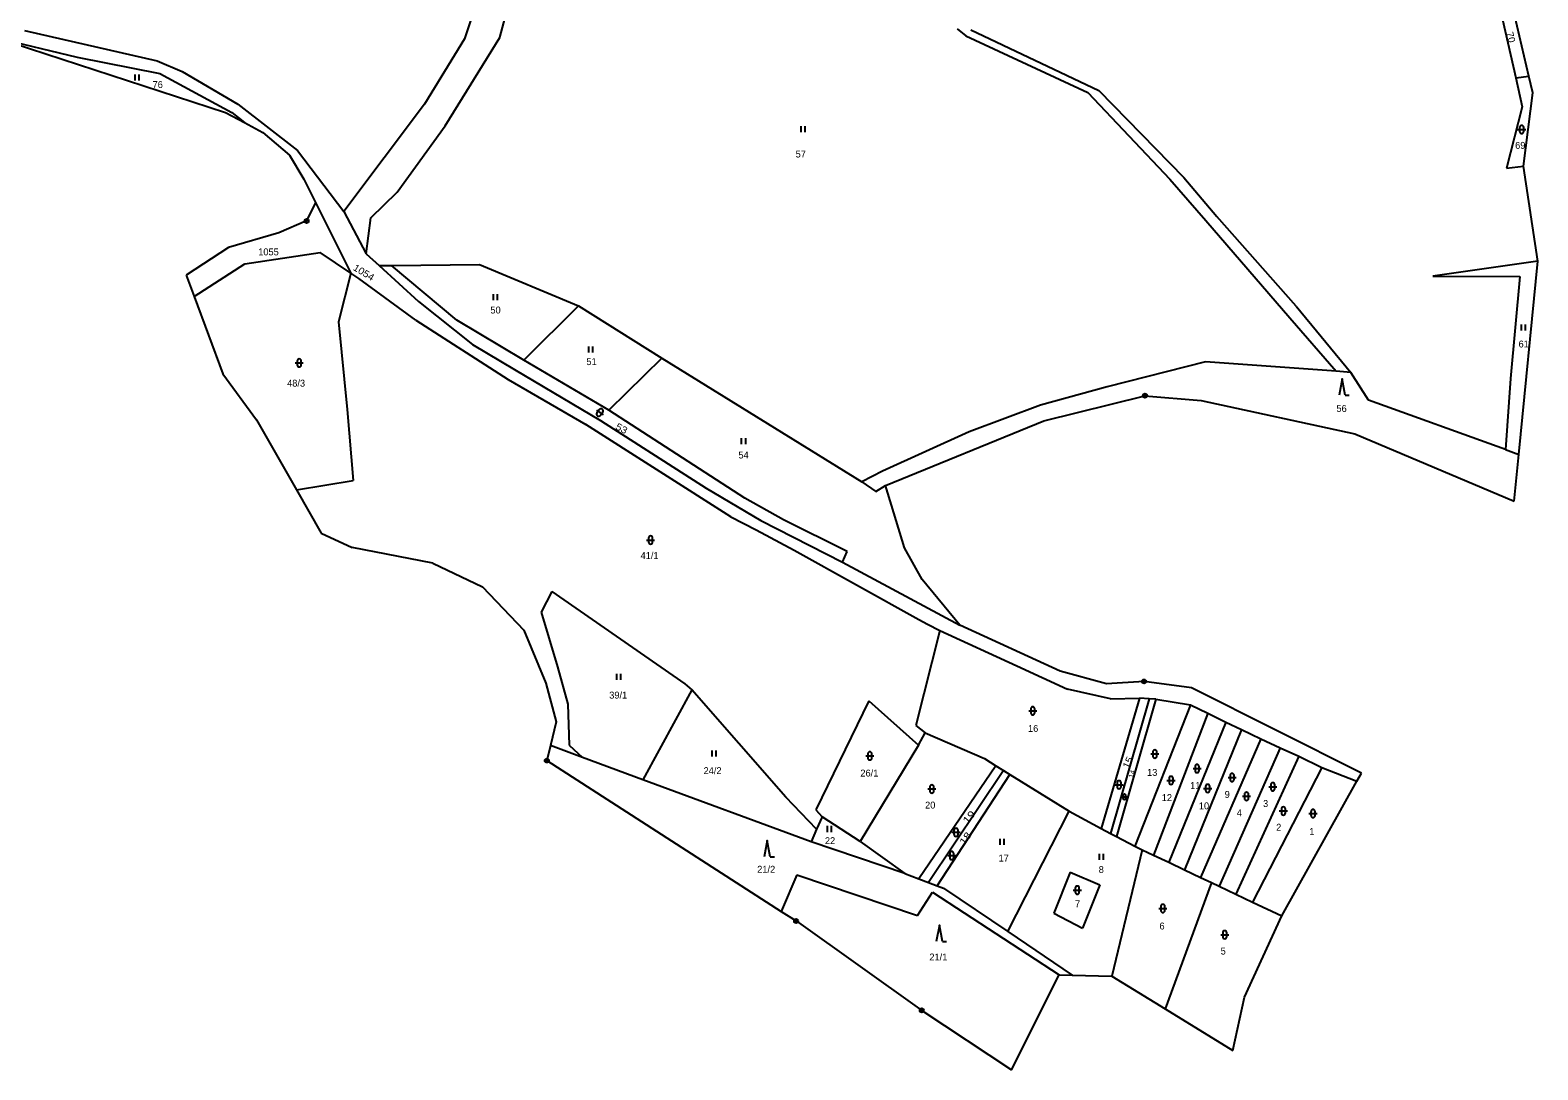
# Model space of a CAD drawing. Extents: x -744132 to -742433, y -984679 to -982287.
# Drawn here: x -742804.5 to -742433.4, y -984679 to -984423.2 of the extents above; entities that cross this region are included whole.
import ezdxf

# ---------------------------------------------------------------- set-up
doc = ezdxf.new("R2010")
doc.units = 0
doc.header["$LTSCALE"] = 0.68
for name, color, linetype, lineweight in [('1', 7, 'Continuous', 25), ('3', 7, 'Continuous', 25), ('8', 7, 'Continuous', 25)]:
    doc.layers.add(name, color=color, linetype=linetype, lineweight=lineweight)
doc.layers.add('2', color=7, linetype='Continuous')

msp = doc.modelspace()

# ---------------------------------------------------------------- linework, layer by layer
at = {"layer": '1'}
for p, q in [((-742686.64, -984392.91), (-742697.63, -984425.32)), ((-742688.87, -984424.99), (-742683.18, -984403.1)), ((-742443.84, -984412.74), (-742438.78, -984434.87)), ((-742435.57, -984434.53), (-742440.79, -984412.23)), ((-742805.92, -984423.24), (-742773.27, -984430.71)), ((-742576.33, -984422.81), (-742574.19, -984424.53)), ((-742572.92, -984423.1), (-742541.44, -984438.02)), ((-742812.82, -984425.09), (-742756.42, -984443.42)), ((-742812.82, -984425.09), (-742792.97, -984429.85)), ((-742697.63, -984425.32), (-742707.47, -984441.42)), ((-742702.33, -984446.74), (-742688.87, -984424.99)), ((-742574.19, -984424.53), (-742544.19, -984438.51)), ((-742792.97, -984429.85), (-742772.63, -984433.86)), ((-742773.27, -984430.71), (-742767.1, -984433.32)), ((-742772.63, -984433.86), (-742754.86, -984443.45)), ((-742767.1, -984433.32), (-742753.38, -984441.39)), ((-742438.78, -984434.87), (-742435.57, -984434.53)), ((-742438.78, -984434.87), (-742437.22, -984442.01)), ((-742434.62, -984438.58), (-742435.57, -984434.53)), ((-742544.19, -984438.51), (-742523.93, -984459.88)), ((-742541.44, -984438.02), (-742520.52, -984459.47)), ((-742436.89, -984456.67), (-742434.62, -984438.58)), ((-742753.38, -984441.39), (-742738.7, -984452.76)), ((-742707.47, -984441.42), (-742727.28, -984467.78)), ((-742437.22, -984442.01), (-742441.06, -984457.16)), ((-742756.42, -984443.42), (-742751.74, -984445.92)), ((-742754.86, -984443.45), (-742751.74, -984445.92)), ((-742751.74, -984445.92), (-742747.24, -984448.32)), ((-742747.24, -984448.32), (-742740.7, -984453.97)), ((-742714.21, -984463.04), (-742702.33, -984446.74)), ((-742740.7, -984453.97), (-742737.18, -984459.85)), ((-742441.06, -984457.16), (-742436.89, -984456.67)), ((-742433.38, -984480), (-742436.89, -984456.67)), ((-742737.18, -984459.85), (-742734.28, -984465.58)), ((-742523.93, -984459.88), (-742515.07, -984470.05)), ((-742520.52, -984459.47), (-742512.4, -984469)), ((-742720.62, -984469.38), (-742714.21, -984463.04)), ((-742734.28, -984465.58), (-742736.47, -984470.13)), ((-742734.28, -984465.58), (-742725.54, -984483)), ((-742736.47, -984470.13), (-742743.28, -984473.08)), ((-742721.84, -984478.21), (-742720.62, -984469.38)), ((-742515.07, -984470.05), (-742494.47, -984493.95)), ((-742492.9, -984491.09), (-742512.4, -984469)), ((-742743.28, -984473.08), (-742755.72, -984476.65)), ((-742755.72, -984476.65), (-742766.07, -984483.46)), ((-742751.7, -984480.69), (-742733.14, -984477.92)), ((-742725.54, -984483), (-742733.14, -984477.92)), ((-742721.84, -984478.21), (-742718.62, -984481.12)), ((-742433.38, -984480), (-742459.23, -984483.72)), ((-742438.1, -984527.59), (-742433.38, -984480)), ((-742766.07, -984483.46), (-742764.15, -984488.68)), ((-742764.15, -984488.68), (-742751.7, -984480.69)), ((-742725.54, -984483), (-742728.62, -984494.92)), ((-742723.64, -984484.28), (-742725.54, -984483)), ((-742718.62, -984481.12), (-742715.55, -984481.06)), ((-742718.62, -984481.12), (-742708.88, -984489.94)), ((-742715.55, -984481.06), (-742693.94, -984480.84)), ((-742699.46, -984494.54), (-742715.55, -984481.06)), ((-742693.94, -984480.84), (-742669.5, -984491)), ((-742459.23, -984483.72), (-742437.82, -984483.8)), ((-742437.82, -984483.8), (-742440.08, -984508.93)), ((-742709.61, -984494.5), (-742723.64, -984484.28)), ((-742764.15, -984488.68), (-742757.11, -984507.78)), ((-742708.88, -984489.94), (-742695.61, -984500.55)), ((-742669.5, -984491), (-742682.95, -984504.39)), ((-742669.5, -984491), (-742649.04, -984503.92)), ((-742492.9, -984491.09), (-742479.4, -984507.38)), ((-742728.62, -984494.92), (-742726.49, -984516.5)), ((-742709.61, -984494.5), (-742686.88, -984509.16)), ((-742682.95, -984504.39), (-742699.46, -984494.54)), ((-742494.47, -984493.95), (-742483.02, -984507.12)), ((-742695.61, -984500.55), (-742685.32, -984506.7)), ((-742662.08, -984516.66), (-742682.95, -984504.39)), ((-742649.04, -984503.92), (-742662.08, -984516.66)), ((-742649.04, -984503.92), (-742599.77, -984534.36)), ((-742515.19, -984504.78), (-742539.43, -984510.92)), ((-742483.02, -984507.12), (-742515.19, -984504.78)), ((-742757.11, -984507.78), (-742748.76, -984519.05)), ((-742686.88, -984509.16), (-742667.69, -984520.25)), ((-742685.32, -984506.7), (-742664.11, -984519.23)), ((-742479.4, -984507.38), (-742483.02, -984507.12)), ((-742475.08, -984514.22), (-742479.4, -984507.38)), ((-742440.08, -984508.93), (-742441.34, -984526.33)), ((-742539.43, -984510.92), (-742555.77, -984515.48)), ((-742554.97, -984519.32), (-742530.1, -984513.12)), ((-742530.1, -984513.12), (-742516.26, -984514.3)), ((-742726.49, -984516.5), (-742725, -984533.99)), ((-742628.57, -984538.37), (-742662.08, -984516.66)), ((-742555.77, -984515.48), (-742573.38, -984522.02)), ((-742516.26, -984514.3), (-742478.43, -984522.49)), ((-742441.34, -984526.33), (-742475.08, -984514.22)), ((-742748.76, -984519.05), (-742738.91, -984536.33)), ((-742632, -984542.91), (-742667.69, -984520.25)), ((-742664.11, -984519.23), (-742638.1, -984535.86)), ((-742593.93, -984535.26), (-742554.97, -984519.32)), ((-742573.38, -984522.02), (-742594.73, -984531.71)), ((-742478.43, -984522.49), (-742439.24, -984539.06)), ((-742441.34, -984526.33), (-742438.1, -984527.59)), ((-742439.24, -984539.06), (-742438.1, -984527.59)), ((-742594.73, -984531.71), (-742599.77, -984534.36)), ((-742738.91, -984536.33), (-742725, -984533.99)), ((-742599.77, -984534.36), (-742596.31, -984536.74)), ((-742596.31, -984536.74), (-742593.93, -984535.26)), ((-742589.29, -984550.55), (-742593.93, -984535.26)), ((-742738.91, -984536.33), (-742732.87, -984546.93)), ((-742638.1, -984535.86), (-742624.66, -984543.84)), ((-742619.11, -984543.68), (-742628.57, -984538.37)), ((-742632, -984542.91), (-742625.81, -984546.14)), ((-742625.81, -984546.14), (-742616.44, -984551.15)), ((-742624.66, -984543.84), (-742604.56, -984554.07)), ((-742603.41, -984551.46), (-742619.11, -984543.68)), ((-742732.87, -984546.93), (-742725.28, -984550.46)), ((-742705.39, -984554.38), (-742725.28, -984550.46)), ((-742584.9, -984558.39), (-742589.29, -984550.55)), ((-742616.44, -984551.15), (-742585.78, -984568.2)), ((-742604.56, -984554.07), (-742603.41, -984551.46)), ((-742604.56, -984554.07), (-742575.65, -984569.59)), ((-742705.39, -984554.38), (-742693.14, -984560.18)), ((-742693.14, -984560.18), (-742683.01, -984570.81)), ((-742676.11, -984561.3), (-742678.71, -984566.36)), ((-742676.11, -984561.3), (-742643.34, -984584)), ((-742575.65, -984569.59), (-742584.9, -984558.39)), ((-742678.71, -984566.36), (-742674.71, -984579.83)), ((-742585.78, -984568.2), (-742583.65, -984569.34)), ((-742683.01, -984570.81), (-742677.6, -984583.87)), ((-742580.59, -984570.91), (-742561.67, -984579.62)), ((-742550.93, -984580.91), (-742575.65, -984569.59)), ((-742674.71, -984579.83), (-742672.17, -984589)), ((-742561.67, -984579.62), (-742549.17, -984585.35)), ((-742677.6, -984583.87), (-742675.07, -984593.37)), ((-742643.34, -984584), (-742641.62, -984585.48)), ((-742539.6, -984584.04), (-742550.93, -984580.91)), ((-742530.31, -984583.45), (-742539.6, -984584.04)), ((-742518.63, -984584.98), (-742530.31, -984583.45)), ((-742641.62, -984585.48), (-742653.69, -984607.63)), ((-742618.47, -984611.95), (-742641.62, -984585.48)), ((-742538.6, -984587.71), (-742549.17, -984585.35)), ((-742531.44, -984587.6), (-742540.9, -984619.6)), ((-742538.6, -984587.71), (-742531.44, -984587.6)), ((-742529.05, -984587.71), (-742538.55, -984620.83)), ((-742529.05, -984587.71), (-742531.44, -984587.6)), ((-742527.43, -984587.79), (-742529.05, -984587.71)), ((-742476.82, -984606.04), (-742518.63, -984584.98)), ((-742672.17, -984589), (-742671.81, -984599.12)), ((-742598.03, -984588.23), (-742611.11, -984615.06)), ((-742598.03, -984588.23), (-742585.85, -984599.09)), ((-742527.43, -984587.79), (-742537.11, -984621.58)), ((-742518.91, -984589.19), (-742532.55, -984624.01)), ((-742514.6, -984591.28), (-742528.03, -984626.16)), ((-742527.43, -984587.79), (-742518.91, -984589.19)), ((-742518.91, -984589.19), (-742514.6, -984591.28)), ((-742514.6, -984591.28), (-742510.17, -984593.43)), ((-742675.07, -984593.37), (-742676.46, -984599.25)), ((-742586.52, -984594.31), (-742584.19, -984596.12)), ((-742510.17, -984593.43), (-742524.24, -984627.96)), ((-742510.17, -984593.43), (-742506.32, -984595.3)), ((-742585.85, -984599.09), (-742584.19, -984596.12)), ((-742584.19, -984596.12), (-742569.62, -984602.45)), ((-742506.32, -984595.3), (-742520.34, -984629.81)), ((-742501.58, -984597.6), (-742516.43, -984631.66)), ((-742506.32, -984595.3), (-742501.58, -984597.6)), ((-742501.58, -984597.6), (-742496.8, -984599.79)), ((-742676.46, -984599.25), (-742677.33, -984602.93)), ((-742668.52, -984602.17), (-742676.46, -984599.25)), ((-742671.81, -984599.12), (-742668.52, -984602.17)), ((-742653.69, -984607.63), (-742668.52, -984602.17)), ((-742585.85, -984599.09), (-742600.21, -984622.87)), ((-742569.62, -984602.45), (-742566.78, -984604.21)), ((-742496.8, -984599.79), (-742511.82, -984633.84)), ((-742492.21, -984601.87), (-742507.73, -984635.78)), ((-742496.8, -984599.79), (-742492.21, -984601.87)), ((-742492.21, -984601.87), (-742486.59, -984604.65)), ((-742677.33, -984602.93), (-742619.64, -984640.05)), ((-742566.78, -984604.21), (-742585.76, -984632.01)), ((-742564.94, -984605.35), (-742583.38, -984632.94)), ((-742566.78, -984604.21), (-742564.94, -984605.35)), ((-742564.94, -984605.35), (-742563.36, -984606.33)), ((-742486.59, -984604.65), (-742503.61, -984637.74)), ((-742486.59, -984604.65), (-742477.9, -984607.97)), ((-742477.9, -984607.97), (-742476.82, -984606.04)), ((-742612.28, -984622.88), (-742653.69, -984607.63)), ((-742581.28, -984633.76), (-742563.36, -984606.33)), ((-742563.36, -984606.33), (-742548.73, -984615.39)), ((-742496.41, -984641.15), (-742477.9, -984607.97)), ((-742610.97, -984619.82), (-742618.47, -984611.95)), ((-742611.11, -984615.06), (-742609.55, -984616.79)), ((-742609.55, -984616.79), (-742610.97, -984619.82)), ((-742600.21, -984622.87), (-742609.55, -984616.79)), ((-742563.81, -984645.01), (-742548.73, -984615.39)), ((-742548.73, -984615.39), (-742540.9, -984619.6)), ((-742610.97, -984619.82), (-742612.28, -984622.88)), ((-742540.9, -984619.6), (-742538.55, -984620.83)), ((-742538.55, -984620.83), (-742537.11, -984621.58)), ((-742589.18, -984630.69), (-742612.28, -984622.88)), ((-742600.21, -984622.87), (-742589.18, -984630.69)), ((-742537.11, -984621.58), (-742532.55, -984624.01)), ((-742532.55, -984624.01), (-742530.75, -984624.87)), ((-742530.75, -984624.87), (-742538.23, -984655.97)), ((-742530.75, -984624.87), (-742528.03, -984626.16)), ((-742528.03, -984626.16), (-742524.24, -984627.96)), ((-742524.24, -984627.96), (-742520.34, -984629.81)), ((-742615.82, -984631.07), (-742619.64, -984640.05)), ((-742615.82, -984631.07), (-742586.11, -984641.07)), ((-742589.18, -984630.69), (-742585.76, -984632.01)), ((-742585.76, -984632.01), (-742583.38, -984632.94)), ((-742548.52, -984630.36), (-742552.49, -984640.45)), ((-742548.52, -984630.36), (-742541.17, -984633.54)), ((-742520.34, -984629.81), (-742516.43, -984631.66)), ((-742516.43, -984631.66), (-742513.71, -984632.95)), ((-742586.11, -984641.07), (-742582.36, -984635.29)), ((-742583.38, -984632.94), (-742581.28, -984633.76)), ((-742582.36, -984635.29), (-742551.21, -984655.68)), ((-742581.28, -984633.76), (-742579.67, -984634.36)), ((-742579.67, -984634.36), (-742563.81, -984645.01)), ((-742541.17, -984633.54), (-742545.44, -984644.15)), ((-742513.71, -984632.95), (-742525.09, -984664.05)), ((-742513.71, -984632.95), (-742511.82, -984633.84)), ((-742511.82, -984633.84), (-742507.73, -984635.78)), ((-742507.73, -984635.78), (-742503.61, -984637.74)), ((-742503.61, -984637.74), (-742496.41, -984641.15)), ((-742619.64, -984640.05), (-742615.98, -984642.4)), ((-742615.98, -984642.4), (-742585.04, -984664.39)), ((-742552.49, -984640.45), (-742545.44, -984644.15)), ((-742505.61, -984661.14), (-742496.41, -984641.15)), ((-742563.81, -984645.01), (-742547.99, -984655.75)), ((-742562.98, -984679.03), (-742551.21, -984655.68)), ((-742551.21, -984655.68), (-742547.99, -984655.75)), ((-742547.99, -984655.75), (-742538.23, -984655.97)), ((-742538.23, -984655.97), (-742525.09, -984664.05)), ((-742508.48, -984674.26), (-742505.61, -984661.14)), ((-742585.04, -984664.39), (-742562.98, -984679.03)), ((-742525.09, -984664.05), (-742508.48, -984674.26))]:
    msp.add_line(p, q, dxfattribs=at)
for points in [[(-742738.7, -984452.76), (-742727.28, -984467.78), (-742721.84, -984478.21)], [(-742583.65, -984569.34), (-742580.59, -984570.91), (-742586.52, -984594.31)]]:
    msp.add_lwpolyline(points, dxfattribs=at)
at = {"layer": '3'}
for p, q in [((-742778.701, -984435.57), (-742778.701, -984434.07)), ((-742777.7, -984435.57), (-742777.7, -984434.07)), ((-742614.741, -984448.27), (-742614.741, -984446.77)), ((-742613.74, -984448.27), (-742613.74, -984446.77)), ((-742438.361, -984447.611), (-742436.359, -984447.611)), ((-742437.861, -984447.111), (-742437.861, -984448.112)), ((-742436.859, -984448.112), (-742436.859, -984447.111)), ((-742690.481, -984489.6), (-742690.481, -984488.1)), ((-742689.48, -984489.6), (-742689.48, -984488.1)), ((-742437.391, -984497.08), (-742437.391, -984495.58)), ((-742436.39, -984497.08), (-742436.39, -984495.58)), ((-742667.001, -984502.51), (-742667.001, -984501.01)), ((-742666, -984502.51), (-742666, -984501.01)), ((-742739.281, -984505.061), (-742737.279, -984505.061)), ((-742738.781, -984504.561), (-742738.781, -984505.562)), ((-742737.779, -984505.562), (-742737.779, -984504.561)), ((-742480.8, -984513), (-742479.804, -984513)), ((-742665.093, -984516.673), (-742663.473, -984517.85)), ((-742664.394, -984516.563), (-742664.982, -984517.373)), ((-742664.172, -984517.961), (-742663.584, -984517.151)), ((-742629.381, -984525.07), (-742629.381, -984523.57)), ((-742628.38, -984525.07), (-742628.38, -984523.57)), ((-742652.791, -984548.641), (-742650.789, -984548.641)), ((-742652.291, -984548.141), (-742652.291, -984549.142)), ((-742651.289, -984549.142), (-742651.289, -984548.141)), ((-742660.131, -984583.09), (-742660.131, -984581.59)), ((-742659.13, -984583.09), (-742659.13, -984581.59)), ((-742558.711, -984590.681), (-742556.709, -984590.681)), ((-742558.211, -984590.181), (-742558.211, -984591.182)), ((-742557.209, -984591.182), (-742557.209, -984590.181)), ((-742636.671, -984601.91), (-742636.671, -984600.41)), ((-742635.67, -984601.91), (-742635.67, -984600.41)), ((-742598.811, -984601.771), (-742596.809, -984601.771)), ((-742598.311, -984601.271), (-742598.311, -984602.272)), ((-742597.309, -984602.272), (-742597.309, -984601.271)), ((-742528.661, -984601.291), (-742526.659, -984601.291)), ((-742528.161, -984600.791), (-742528.161, -984601.792)), ((-742527.159, -984601.792), (-742527.159, -984600.791)), ((-742518.261, -984604.881), (-742516.259, -984604.881)), ((-742517.761, -984604.381), (-742517.761, -984605.382)), ((-742516.759, -984605.382), (-742516.759, -984604.381)), ((-742583.551, -984609.911), (-742581.549, -984609.911)), ((-742583.051, -984609.411), (-742583.051, -984610.412)), ((-742582.049, -984610.412), (-742582.049, -984609.411)), ((-742537.461, -984608.871), (-742535.459, -984608.871)), ((-742536.961, -984608.371), (-742536.961, -984609.372)), ((-742535.959, -984609.372), (-742535.959, -984608.371)), ((-742524.671, -984607.801), (-742522.669, -984607.801)), ((-742524.171, -984607.301), (-742524.171, -984608.302)), ((-742523.169, -984608.302), (-742523.169, -984607.301)), ((-742515.651, -984609.771), (-742513.649, -984609.771)), ((-742515.151, -984609.271), (-742515.151, -984610.272)), ((-742514.149, -984610.272), (-742514.149, -984609.271)), ((-742509.651, -984607.081), (-742507.649, -984607.081)), ((-742509.151, -984606.581), (-742509.151, -984607.582)), ((-742508.149, -984607.582), (-742508.149, -984606.581)), ((-742499.631, -984609.371), (-742497.629, -984609.371)), ((-742499.131, -984608.871), (-742499.131, -984609.872)), ((-742498.129, -984609.872), (-742498.129, -984608.871)), ((-742535.861, -984611.831), (-742534.459, -984611.831)), ((-742535.51, -984611.48), (-742535.51, -984612.181)), ((-742534.81, -984612.181), (-742534.81, -984611.48)), ((-742506.101, -984611.721), (-742504.099, -984611.721)), ((-742505.601, -984611.221), (-742505.601, -984612.222)), ((-742504.599, -984612.222), (-742504.599, -984611.221)), ((-742497.021, -984615.321), (-742495.019, -984615.321)), ((-742496.521, -984614.821), (-742496.521, -984615.822)), ((-742495.519, -984615.822), (-742495.519, -984614.821)), ((-742489.721, -984615.951), (-742487.719, -984615.951)), ((-742489.221, -984615.451), (-742489.221, -984616.452)), ((-742488.219, -984616.452), (-742488.219, -984615.451)), ((-742608.241, -984620.5), (-742608.241, -984619)), ((-742607.24, -984620.5), (-742607.24, -984619)), ((-742577.601, -984620.581), (-742575.599, -984620.581)), ((-742577.101, -984620.081), (-742577.101, -984621.082)), ((-742576.099, -984621.082), (-742576.099, -984620.081)), ((-742565.771, -984623.65), (-742565.771, -984622.15)), ((-742564.77, -984623.65), (-742564.77, -984622.15)), ((-742622.32, -984626.57), (-742621.324, -984626.57)), ((-742578.651, -984626.291), (-742576.649, -984626.291)), ((-742578.151, -984625.791), (-742578.151, -984626.792)), ((-742577.149, -984626.792), (-742577.149, -984625.791)), ((-742541.291, -984627.35), (-742541.291, -984625.85)), ((-742540.29, -984627.35), (-742540.29, -984625.85)), ((-742547.751, -984634.801), (-742545.749, -984634.801)), ((-742547.251, -984634.301), (-742547.251, -984635.302)), ((-742546.249, -984635.302), (-742546.249, -984634.301)), ((-742526.701, -984639.311), (-742524.699, -984639.311)), ((-742526.201, -984638.811), (-742526.201, -984639.812)), ((-742525.199, -984639.812), (-742525.199, -984638.811)), ((-742511.451, -984645.781), (-742509.449, -984645.781)), ((-742510.951, -984645.281), (-742510.951, -984646.282)), ((-742509.949, -984646.282), (-742509.949, -984645.281)), ((-742579.96, -984647.45), (-742578.964, -984647.45))]:
    msp.add_line(p, q, dxfattribs=at)
for points in [[(-742480.8, -984513), (-742481.55, -984509), (-742482.3, -984513)], [(-742622.32, -984626.57), (-742623.07, -984622.57), (-742623.82, -984626.57)], [(-742579.96, -984647.45), (-742580.71, -984643.45), (-742581.46, -984647.45)]]:
    msp.add_lwpolyline(points, dxfattribs=at)
for centre, radius, start, end in [((-742437.36, -984447.1109), 0.5, 0, 180), ((-742437.36, -984448.1109), 0.5, 180, 359.98789), ((-742738.28, -984504.5609), 0.5, 0, 180), ((-742738.28, -984505.5609), 0.5, 180, 359.98789), ((-742663.9889, -984516.8572), 0.5, 324, 144), ((-742664.5766, -984517.6662), 0.5, 144, 323.98789), ((-742651.79, -984548.1409), 0.5, 0, 180), ((-742651.79, -984549.1409), 0.5, 180, 359.98789), ((-742557.71, -984590.1809), 0.5, 0, 180), ((-742557.71, -984591.1809), 0.5, 180, 359.98789), ((-742597.81, -984601.2709), 0.5, 0, 180), ((-742597.81, -984602.2709), 0.5, 180, 359.98789), ((-742527.66, -984600.7909), 0.5, 0, 180), ((-742527.66, -984601.7909), 0.5, 180, 359.98789), ((-742517.26, -984604.3809), 0.5, 0, 180), ((-742517.26, -984605.3809), 0.5, 180, 359.98789), ((-742508.65, -984606.5809), 0.5, 0, 180), ((-742582.55, -984609.4109), 0.5, 0, 180), ((-742536.46, -984608.3709), 0.5, 0, 180), ((-742536.46, -984609.3709), 0.5, 180, 359.98789), ((-742523.67, -984607.3009), 0.5, 0, 180), ((-742523.67, -984608.3009), 0.5, 180, 359.98789), ((-742514.65, -984609.2709), 0.5, 0, 180), ((-742508.65, -984607.5809), 0.5, 180, 359.98789), ((-742498.63, -984608.8709), 0.5, 0, 180), ((-742498.63, -984609.8709), 0.5, 180, 359.98789), ((-742582.55, -984610.4109), 0.5, 180, 359.98789), ((-742535.16, -984611.4806), 0.35, 0, 180), ((-742535.16, -984612.1806), 0.35, 180, 359.98789), ((-742514.65, -984610.2709), 0.5, 180, 359.98789), ((-742505.1, -984611.2209), 0.5, 0, 180), ((-742505.1, -984612.2209), 0.5, 180, 359.98789), ((-742496.02, -984614.8209), 0.5, 0, 180), ((-742496.02, -984615.8209), 0.5, 180, 359.98789), ((-742488.72, -984615.4509), 0.5, 0, 180), ((-742488.72, -984616.4509), 0.5, 180, 359.98789), ((-742576.6, -984620.0809), 0.5, 0, 180), ((-742576.6, -984621.0809), 0.5, 180, 359.98789), ((-742577.65, -984625.7909), 0.5, 0, 180), ((-742577.65, -984626.7909), 0.5, 180, 359.98789), ((-742546.75, -984634.3009), 0.5, 0, 180), ((-742546.75, -984635.3009), 0.5, 180, 359.98789), ((-742525.7, -984638.8109), 0.5, 0, 180), ((-742525.7, -984639.8109), 0.5, 180, 359.98789), ((-742510.45, -984645.2809), 0.5, 0, 180), ((-742510.45, -984646.2809), 0.5, 180, 359.98789)]:
    msp.add_arc(centre, radius, start, end, dxfattribs=at)
at = {"layer": '8'}
for centre, radius in [((-742736.47, -984470.1299), 0.5), ((-742736.47, -984470.1299), 0.0303), ((-742530.1, -984513.1199), 0.5), ((-742530.1, -984513.1199), 0.0303), ((-742530.31, -984583.4499), 0.5), ((-742530.31, -984583.4499), 0.0303), ((-742677.33, -984602.9299), 0.5), ((-742677.33, -984602.9299), 0.0303), ((-742615.98, -984642.3999), 0.5), ((-742615.98, -984642.3999), 0.0303), ((-742585.04, -984664.3899), 0.5), ((-742585.04, -984664.3899), 0.0303)]:
    msp.add_circle(centre, radius, dxfattribs=at)

# ---------------------------------------------------------------- texts
at = {"layer": '2'}
for s, height, rotation, width, p in [('70', 1.7, 284, 1.05, (-742441.162, -984423.822)), ('1054', 1.7, 329, 1.1, (-742725.198, -984482.084)), ('53', 1.7, 332, 1.15, (-742660.609, -984521.265)), ('15', 1.7, 65, 1.15, (-742534.134, -984605.069)), ('14', 1.19, 75, 1.1, (-742532.982, -984607.316)), ('19', 1.7, 49, 1.3, (-742573.839, -984618.628)), ('18', 1.7, 54, 1.25, (-742574.536, -984623.839))]:
    msp.add_text(s, height=height, rotation=rotation, dxfattribs=dict(at, width=width)).set_placement(p)
for s, p in [('76', (-742774.38, -984437.405)), ('57', (-742616.08, -984454.505)), ('69', (-742438.97, -984452.375)), ('1055', (-742748.38, -984478.585)), ('50', (-742691.22, -984492.895)), ('61', (-742438.13, -984501.255)), ('51', (-742667.59, -984505.595)), ('48/3', (-742741.26, -984510.895)), ('56', (-742482.96, -984517.125)), ('54', (-742630.17, -984528.575)), ('41/1', (-742654.25, -984553.315)), ('39/1', (-742661.97, -984587.665)), ('16', (-742558.88, -984595.865)), ('24/2', (-742638.75, -984606.255)), ('26/1', (-742600.15, -984606.845)), ('13', (-742529.58, -984606.685)), ('11', (-742518.97, -984609.905)), ('20', (-742584.22, -984614.725)), ('12', (-742525.96, -984612.885)), ('10', (-742516.83, -984614.915)), ('9', (-742510.47, -984612.105)), ('3', (-742501.03, -984614.345)), ('4', (-742507.5, -984616.645)), ('2', (-742497.8, -984620.185)), ('1', (-742489.66, -984621.235)), ('22', (-742608.88, -984623.485)), ('17', (-742566.14, -984627.775)), ('21/2', (-742625.54, -984630.525)), ('8', (-742541.48, -984630.595)), ('7', (-742547.31, -984639.005)), ('6', (-742526.52, -984644.485)), ('21/1', (-742583.17, -984652.115)), ('5', (-742511.46, -984650.655))]:
    msp.add_text(s, height=1.7, dxfattribs=at).set_placement(p)

doc.saveas('drawing.dxf')
